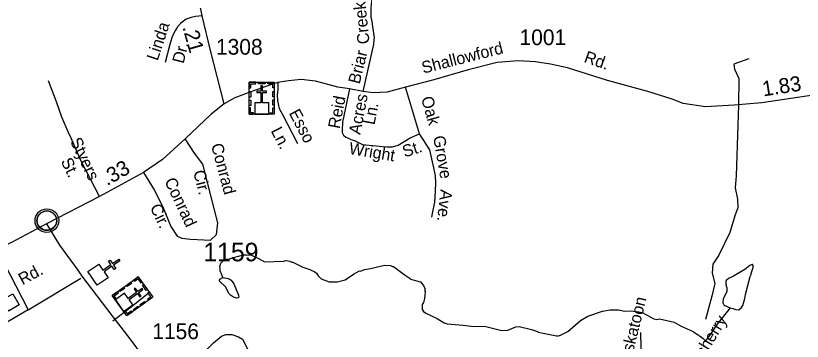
# Model space of a CAD drawing. Extents: x 1547597 to 1699558, y 810033 to 920809.
# Drawn here: x 1580417 to 1586678, y 856344 to 858935 of the extents above; entities that cross this region are included whole.
import ezdxf

# ---------------------------------------------------------------- set-up
doc = ezdxf.new("R2010")
doc.units = 0
for name, color, linetype in [('Exist Civil Demographics Community CELL', 7, 'Continuous'), ('Exist Cultural Church CELL', 7, 'Continuous'), ('Exist Cultural Church with Cemetery CELL', 7, 'Continuous'), ('Exist Cultural Educational Facility Elementary CELL', 7, 'Continuous'), ('Exist Hydrographic Misc Water Feature', 7, 'Continuous'), ('Exist Road Non-System Type 51', 7, 'Continuous'), ('Exist Road Non-System Type 51 Label', 7, 'Continuous'), ('Exist Road Secondary Historical Relocated Label', 7, 'Continuous'), ('Exist Road Secondary Mileage Hundredths English Label', 7, 'Continuous'), ('Exist Road Secondary Type 51 Attributed', 7, 'Continuous'), ('Exist Road Secondary Type 51 Label', 7, 'Continuous'), ('Exist Road Secondary Type 51 Number Label', 7, 'Continuous')]:
    doc.layers.add(name, color=color, linetype=linetype)

msp = doc.modelspace()

# ---------------------------------------------------------------- linework, layer by layer
at = {"layer": 'Exist Civil Demographics Community CELL'}
msp.add_lwpolyline([(1580586.7, 857316.5), (1580587.7, 857322.1), (1580589.5, 857328.7), (1580592.4, 857335.9), (1580595.3, 857341.6), (1580598.7, 857347.4), (1580602.4, 857352.5), (1580606.4, 857356.9), (1580611, 857361.4), (1580616.5, 857366), (1580621.9, 857369.7), (1580626.8, 857372.6), (1580631.9, 857375), (1580637.3, 857377.3), (1580643, 857379.1), (1580647.3, 857380.3), (1580652.1, 857381), (1580656.3, 857381.7), (1580662.6, 857382), (1580667.1, 857381.9), (1580672.7, 857381.6), (1580677.6, 857380.9), (1580682.5, 857379.9), (1580687.5, 857378.5), (1580692.7, 857376.6), (1580699.4, 857373.7), (1580705.6, 857370.2), (1580710.7, 857366.6), (1580715.9, 857362.6), (1580719.2, 857359.5), (1580723.3, 857355.1), (1580727.1, 857350.4), (1580730.2, 857345.8), (1580733.4, 857340.8), (1580735.8, 857335.6), (1580737.8, 857330.6), (1580739.4, 857325.6), (1580740.7, 857321), (1580741.8, 857315), (1580742.4, 857310.3), (1580742.7, 857304.3), (1580742.5, 857298.5), (1580741.9, 857292.8), (1580741, 857287.3), (1580739.3, 857281.1), (1580737.5, 857275.3), (1580735.2, 857270.2), (1580732, 857264.2), (1580728.7, 857258.9), (1580725.3, 857254.2), (1580721, 857249.5), (1580715.7, 857244.5), (1580710.7, 857240.4), (1580705.7, 857236.9), (1580701.4, 857234.4), (1580694.6, 857231.2), (1580687.4, 857228.5), (1580681.5, 857227), (1580674.9, 857225.7), (1580670.5, 857225.3), (1580666, 857225), (1580660.4, 857225), (1580656.1, 857225.4), (1580650.5, 857226.1), (1580644.5, 857227.4), (1580640, 857228.8), (1580634.8, 857230.6), (1580630.2, 857232.6), (1580626.3, 857234.9), (1580619.5, 857238.9), (1580613.9, 857243.2), (1580609, 857247.7), (1580604.5, 857252.5), (1580601.3, 857256.5), (1580598.4, 857260.7), (1580594.3, 857267.8), (1580592.6, 857271.3), (1580590.8, 857275.3), (1580588.2, 857283.5), (1580586.7, 857290.6), (1580586, 857295.7), (1580585.7, 857302.1), (1580585.6, 857306.8), (1580586.2, 857313.2)], close=True, dxfattribs=at)
for centre, radius in [((1580664.3, 857304.1), 94.3), ((1580664.1, 857304.4), 76.7)]:
    msp.add_circle(centre, radius, dxfattribs=at)
at = {"layer": 'Exist Cultural Church CELL'}
msp.add_lwpolyline([(1581078.6, 856957.9), (1581110.8, 856910.9), (1581173.7, 856953.8), (1581155.7, 856980.3), (1581168.9, 856989.3), (1581186.9, 856962.8), (1581236.6, 856996.7), (1581245.6, 856983.4), (1581195.9, 856949.6), (1581214, 856923.1), (1581200.7, 856914.1), (1581182.7, 856940.6), (1581119.8, 856897.7), (1581152.2, 856850), (1581064.2, 856790.1), (1580990.7, 856898)], close=True, dxfattribs=at)
at = {"layer": 'Exist Cultural Church with Cemetery CELL'}
for points in [[(1582275.8, 858405.4), (1582474.9, 858405.4), (1582474.9, 858150.8), (1582275.8, 858150.8)], [(1582275.8, 858362.1), (1582287.2, 858362.1), (1582287.2, 858394.3), (1582327.7, 858394.3), (1582327.7, 858405.4), (1582275.8, 858405.4)], [(1582318.9, 858150.8), (1582431.1, 858150.8), (1582431.1, 858241.4), (1582380.3, 858241.4), (1582380.3, 858322.9), (1582413.3, 858322.9), (1582413.3, 858333.9), (1582380.3, 858333.9), (1582380.3, 858376.1), (1582368.7, 858376.1), (1582368.7, 858333.9), (1582335.6, 858333.9), (1582335.6, 858322.9), (1582368.7, 858322.9), (1582368.7, 858241.4), (1582318.9, 858241.4)], [(1582349.9, 858405.4), (1582401.7, 858405.4), (1582401.7, 858394), (1582349.9, 858394)], [(1582475, 858362), (1582463.6, 858362), (1582463.6, 858394.2), (1582423.1, 858394.2), (1582423.1, 858405.4), (1582475, 858405.4)], [(1582275.8, 858287.9), (1582275.8, 858331.2), (1582287.2, 858331.2), (1582287.2, 858287.9)], [(1582463.6, 858289), (1582463.6, 858332.3), (1582475, 858332.3), (1582475, 858289)], [(1582275.8, 858220.7), (1582275.8, 858264), (1582287.2, 858264), (1582287.2, 858220.7)], [(1582463.5, 858223), (1582463.5, 858266.4), (1582474.9, 858266.4), (1582474.9, 858223)], [(1582308.9, 858150.8), (1582308.9, 858162.3), (1582286.9, 858162.3), (1582286.9, 858202.7), (1582275.8, 858202.7), (1582275.8, 858150.8)], [(1582441.8, 858150.8), (1582441.8, 858162.3), (1582463.8, 858162.3), (1582463.8, 858202.7), (1582474.9, 858202.7), (1582474.9, 858150.8)], [(1581391.7, 856856.8), (1581507.9, 856695.1), (1581301.2, 856546.5), (1581185, 856708.2)], [(1581296.3, 856788.2), (1581331.5, 856813.5), (1581338.1, 856804.3), (1581303, 856779)], [(1581356.5, 856831.5), (1581363.2, 856822.3), (1581389.3, 856841.1), (1581413, 856808.1), (1581422, 856814.6), (1581391.7, 856856.8)], [(1581210.1, 856673.2), (1581275.6, 856582.1), (1581349.1, 856635), (1581319.5, 856676.2), (1581385.7, 856723.8), (1581404.9, 856697), (1581413.9, 856703.4), (1581394.6, 856730.2), (1581428.9, 856754.8), (1581422.1, 856764.2), (1581387.8, 856739.6), (1581368.5, 856766.5), (1581359.6, 856760.1), (1581378.9, 856733.2), (1581312.8, 856685.6), (1581283.7, 856726.1)], [(1581241.7, 856749), (1581276.9, 856774.3), (1581283.5, 856765.1), (1581248.4, 856739.8)], [(1581434.9, 856796.6), (1581465.2, 856754.5), (1581455.9, 856747.9), (1581425.7, 856790)], [(1581204.3, 856681.3), (1581213.6, 856688), (1581200.8, 856705.9), (1581233.6, 856729.5), (1581227.1, 856738.5), (1581185, 856708.2)], [(1581472.7, 856669.8), (1581466.1, 856679), (1581492.3, 856697.8), (1581468.6, 856730.7), (1581477.6, 856737.2), (1581507.9, 856695)], [(1581353.2, 856597.9), (1581388.4, 856623.2), (1581395, 856614), (1581359.8, 856588.7)], [(1581406.7, 856636.4), (1581441.9, 856661.6), (1581448.6, 856652.4), (1581413.4, 856627.1)], [(1581281.8, 856573.4), (1581291.1, 856580.1), (1581304, 856562.3), (1581336.8, 856585.8), (1581343.3, 856576.8), (1581301.2, 856546.5)]]:
    msp.add_lwpolyline(points, close=True, dxfattribs=at)
at = {"layer": 'Exist Cultural Educational Facility Elementary CELL'}
msp.add_lwpolyline([(1580444.2, 856634), (1580359.6, 856584.7), (1580336.4, 856624.5), (1580271.5, 856586.7), (1580274.3, 856533.8), (1580220.5, 856568), (1580331.6, 856632.8), (1580308.4, 856672.5), (1580393, 856721.8)], close=True, dxfattribs=at)
at = {"layer": 'Exist Hydrographic Misc Water Feature'}
for points in [[(1582066.6, 856850.8), (1582056.7, 856873.1), (1582045.1, 856905.2), (1582045.3, 856921.2), (1582041.5, 856935.3), (1582049.8, 856965.1), (1582072.1, 856988.8), (1582094.2, 856996.6), (1582118.2, 857000.3), (1582150.4, 857011.9), (1582230.6, 857030.8), (1582254.6, 857032.5), (1582294.6, 857030), (1582340, 857009.4), (1582388.9, 856982.3), (1582393.9, 856976.8), (1582549.9, 856982.8), (1582565.9, 856986.6), (1582597.9, 856982.2), (1582613.8, 856974), (1582621.8, 856973.9), (1582701.3, 856933), (1582757.1, 856916.2), (1582796.9, 856897.7), (1582810.8, 856885.6), (1582824.5, 856865.4), (1582848.2, 856841.1), (1582912, 856818.3), (1582975.9, 856817.6), (1583040, 856832.7), (1583104.6, 856877.9), (1583152.9, 856903.3), (1583160.9, 856903.2), (1583193, 856914.8), (1583241.1, 856922.1), (1583351.4, 856948.7), (1583401.3, 856948.1), (1583417.2, 856939.9), (1583425.2, 856939.8), (1583508.5, 856874.8), (1583557.4, 856842.9), (1583560, 856838.2), (1583639.8, 856817.2), (1583664.1, 856787.7), (1583676.3, 856759.8), (1583671.1, 856756.8), (1583674.9, 856740.8), (1583674.4, 856708.8), (1583670.1, 856684.8), (1583661.8, 856653), (1583653.6, 856637.1), (1583653.1, 856597.1), (1583657, 856589.1), (1583663, 856581), (1583680.8, 856568.8), (1583772.3, 856525.7), (1583827.8, 856491), (1583851.7, 856482.7), (1583979.6, 856473.1), (1584043.4, 856464.3), (1584159.4, 856462.8), (1584287, 856429.2), (1584335, 856432.6), (1584399.3, 856459.8), (1584423.4, 856461.5), (1584523.1, 856438.2), (1584571.2, 856422.7), (1584574.8, 856417.6), (1584722.5, 856387.8), (1584738.5, 856387.6), (1584754.5, 856391.4), (1584810.8, 856420.6), (1584913.9, 856509.3), (1584972.2, 856544.5), (1585088.7, 856583), (1585148.8, 856594.3), (1585216.7, 856593.4), (1585264.6, 856584.8), (1585312.7, 856586.2), (1585376.6, 856579.4), (1585408.5, 856571), (1585495.8, 856522), (1585519.8, 856517.7), (1585541.9, 856521.4), (1585659.6, 856495.9), (1585715.1, 856463.2), (1585810.6, 856422), (1585814.6, 856416), (1585850.3, 856395.6), (1585858.2, 856387.5), (1585866.1, 856385.4), (1585889.9, 856367.1), (1585908.1, 856348.1)], [(1586105.2, 856608.9), (1586124.7, 856606), (1586148.6, 856597.7), (1586172.6, 856595.4), (1586194.8, 856613.1), (1586205, 856629), (1586221.7, 856684.7), (1586226, 856716.7), (1586263.7, 856860.2), (1586271.9, 856876.1), (1586272, 856884.1), (1586288.6, 856931.8), (1586286.8, 856947.8), (1586282.8, 856953.9), (1586278.9, 856955.9), (1586260.8, 856948.1), (1586220.4, 856914.7), (1586131.8, 856861.8), (1586091.6, 856844.3), (1586073.4, 856826.5), (1586069.3, 856818.6), (1586071, 856794.6), (1586078.7, 856770.5), (1586078.3, 856738.5), (1586049.7, 856682.9), (1586045.3, 856651), (1586055.1, 856634.9), (1586063, 856628.8), (1586105.2, 856608.9)], [(1582066.6, 856850.8), (1582108.4, 856844.4), (1582124.3, 856836.2), (1582132.3, 856830.2), (1582151.8, 856799.9), (1582190.8, 856711.4), (1582192.6, 856695.5), (1582186.5, 856689.5), (1582174.5, 856687.7), (1582150.6, 856694), (1582126.8, 856710.3), (1582114.9, 856722.4), (1582085.6, 856776.8), (1582040.1, 856821.3), (1582038.2, 856829.4), (1582042.3, 856837.3), (1582066.6, 856850.8)], [(1586105.2, 856608.9), (1586001.3, 856479.6), (1585948.4, 856400.3), (1585908.1, 856348.1)]]:
    msp.add_lwpolyline(points, dxfattribs=at)
at = {"layer": 'Exist Road Non-System Type 51'}
for p, q in [((1583631.9, 857996.1), (1583518.4, 858365.6)), ((1580265.5, 857078.7), (1580515, 856593.3)), ((1580515, 856593.3), (1580934.1, 856846.3)), ((1580515, 856593.3), (1580248.8, 856437.3)), ((1582221.8, 856359.7), (1582284.1, 856240.8))]:
    msp.add_line(p, q, dxfattribs=at)
for points in [[(1583182.8, 858331.4), (1583257.6, 858661.3), (1583268.3, 858707.1), (1583270.8, 858743), (1583273, 858763), (1583258.4, 858849.4), (1583253, 858889.3), (1583247.5, 858923.4), (1583246, 858959.5), (1583246.3, 858995.5), (1583249, 859027.5), (1583255.4, 859069.5), (1583264, 859105.4), (1583272.5, 859139.2), (1583276.9, 859161.2), (1583287.5, 859199), (1583297.9, 859231), (1583306.5, 859266.8)], [(1581899.9, 858933.3), (1581846.8, 858929.8), (1581812.6, 858922.3), (1581772.5, 858906.9), (1581732, 858875.5), (1581705.7, 858847.8), (1581689.1, 858819.9), (1581664.6, 858774.4), (1581645.6, 858716.5), (1581607.4, 858563)], [(1586254.2, 858593.3), (1586134.7, 858548.5), (1586139, 858510), (1586173.1, 858435.3), (1586171, 858223.9)], [(1581083.3, 857496), (1580938.4, 857777.2), (1580856.7, 857959.8), (1580833.5, 858010.1), (1580784.9, 858128), (1580741.4, 858249.7), (1580677.7, 858417.8)], [(1582503.5, 858404), (1582502.8, 858350), (1582498.1, 858304), (1582501.4, 858260), (1582507.1, 858233.8), (1582514.6, 858197.9), (1582539.8, 858149.3), (1582660.6, 857917.5)], [(1583074.2, 858353), (1583018.3, 858088), (1583016.6, 858023.6), (1583016.3, 858005.6), (1583027.3, 857985.2), (1583043.9, 857968.5), (1583067, 857960), (1583083.5, 857951.3), (1583113.8, 857942), (1583176.8, 857911.5), (1583339.2, 857893.2), (1583371.4, 857890.7), (1583415.6, 857892.2), (1583461.7, 857905.4), (1583555.6, 857964.6), (1583631.9, 857996.1)], [(1586171, 858223.9), (1586166.7, 858063.7), (1586151.8, 857661.8), (1586145.4, 857565.7), (1586162.5, 857473.9), (1586164.6, 857405.6), (1586145.4, 857350), (1586102.7, 857209.1), (1586013.3, 857028.8), (1585966.4, 856958.3), (1585962.1, 856885.7), (1585983.4, 856804.6), (1585957.8, 856702.1), (1585908.8, 856518.4)], [(1581966.6, 857149), (1582015.3, 857195), (1582026.1, 857286.9), (1581945, 857597.9), (1581907.2, 857754.7), (1581839.7, 857841.3), (1581766.7, 857954.8)], [(1583729.7, 857330.5), (1583734.9, 857359.7), (1583752.4, 857451.6), (1583759.5, 857539.5), (1583760.5, 857605.5), (1583757.4, 857661.6), (1583746.3, 857725.6), (1583714.4, 857868.2), (1583631.9, 857996.1)], [(1581434.4, 857687.1), (1581518.2, 857549.2), (1581585.7, 857419.4), (1581650.5, 857257.2), (1581701.9, 857181.5), (1581739.7, 857165.2), (1581807.2, 857157.1), (1581966.6, 857149)], [(1581190.5, 856507.5), (1581335.3, 856617.7), (1581471.5, 856727.8)], [(1581438.2, 856179.9), (1581486, 856214.7), (1581567.1, 856235), (1581619.2, 856240.8), (1581685.9, 856217.6), (1581755.4, 856197.3), (1581796, 856194.4), (1581845.2, 856203.1), (1581897.4, 856237.9), (1581990.1, 856330.7), (1582053.8, 856385.7), (1582088.6, 856397.3), (1582137.8, 856397.3), (1582190, 856379.9), (1582221.8, 856359.7)], [(1585390.7, 856414.6), (1585392.5, 856289.7), (1585372.9, 856134.6)]]:
    msp.add_lwpolyline(points, dxfattribs=at)
at = {"layer": 'Exist Road Secondary Type 51 Attributed'}
for points in [[(1582077, 858233), (1581966.3, 858658.5), (1581899.9, 858933.3), (1581886.6, 858999.7), (1581873.3, 859123.8), (1581894, 859227.3)], [(1586766.4, 858304.2), (1586356.5, 858241), (1586136.7, 858223), (1585908, 858210.4), (1585729.8, 858237.2), (1585641.5, 858271.5), (1585449.7, 858330.9), (1585127.3, 858419.3), (1584809.5, 858520.2), (1584674.4, 858549), (1584555.6, 858567), (1584416.9, 858576.1), (1584248.1, 858561.7), (1584019.3, 858505.8), (1583745.5, 858424.7), (1583518.4, 858365.6), (1583374.8, 858326), (1583261.3, 858320.6), (1583182.8, 858331.4), (1583074.2, 858353), (1582981.1, 858367.4), (1582802.7, 858414.3), (1582689.3, 858426.9), (1582588.4, 858416.1), (1582503.5, 858404), (1582453.3, 858387.3), (1582289.4, 858329.6), (1582161.5, 858280.9), (1582077, 858233)], [(1582077, 858233), (1581972, 858152.6), (1581766.7, 857954.8), (1581585.8, 857791.2), (1581434.4, 857687.1), (1581083.3, 857496), (1580661, 857279.2)], [(1580661, 857279.2), (1580384.2, 857130.2), (1580265.5, 857078.7), (1580172.6, 857036.3), (1580080.4, 856987.7), (1579807.4, 856837), (1579681.7, 856779.9), (1579542.2, 856705.8), (1579438.7, 856638.1), (1579340, 856585.4), (1579277.3, 856557.6), (1579119.8, 856466.2), (1578923.9, 856398.8), (1578736.4, 856317.6), (1578668.2, 856288.3), (1578502.6, 856229.1), (1578279.3, 856149.5), (1578203.1, 856124.1)], [(1580661, 857279.2), (1580763.8, 857110.2), (1580910.7, 856910), (1580943.1, 856861.3), (1581182.4, 856549.2), (1581306.1, 856387.5), (1581459.7, 856183.6)]]:
    msp.add_lwpolyline(points, dxfattribs=at)

# ---------------------------------------------------------------- texts
at = {"layer": 'Exist Road Non-System Type 51 Label'}
for s, rotation, p in [('Creek', 95.85868, (1583234.1, 858713.7)), ('Linda', 71.83331, (1581546.3, 858571.5)), ('Dr.', 76.02544, (1581752.8, 858549.8)), ('Briar', 76.20859, (1583154.1, 858386.6)), ('Reid', 79.17683, (1582994.7, 858031.1)), ('Acres', 79.17683, (1583159.6, 857984.5)), ('Oak', 285.90414, (1583642.8, 858279.2)), ('Esso', 297.52576, (1582588.9, 858161.6)), ('Ln.', 79.17683, (1583272.6, 858061.9)), ('Ln.', 297.52576, (1582444.7, 858019.8)), ('Styers', 295.54909, (1580846.8, 857938.8)), ('Grove', 279.83866, (1583739.1, 857972.7)), ('Conrad', 284.97251, (1581970.5, 857906.1)), ('Wright', 350.60721, (1583064.9, 857835.3)), ('St.', 17.66637, (1583512.6, 857806.5)), ('St.', 295.54909, (1580773.4, 857777.9)), ('Cir.', 283.96791, (1581828.9, 857693.9)), ('Conrad', 295.15969, (1581598.5, 857620)), ('Ave.', 263.54571, (1583799, 857555.1)), ('Cir.', 295.15969, (1581482.6, 857411.7)), ('Saskatoon', 76.18466, (1585295.5, 856102.3)), ('Chockecherry', 58.7138, (1585675.8, 855844))]:
    msp.add_text(s, height=95, rotation=rotation, dxfattribs=at).set_placement(p)
at = {"layer": 'Exist Road Secondary Historical Relocated Label'}
msp.add_text('1159', height=147.64, dxfattribs=at).set_placement((1581910, 856980.6))
at = {"layer": 'Exist Road Secondary Mileage Hundredths English Label'}
for s, rotation, p in [('.21', 285.96926, (1581742.2, 858844)), ('1.83', 8.75483, (1586368.7, 858292.7)), ('.33', 29.63687, (1581143.6, 857578.3))]:
    msp.add_text(s, height=120, rotation=rotation, dxfattribs=at).set_placement(p)
at = {"layer": 'Exist Road Secondary Type 51 Label'}
for s, rotation, p in [('Shallowford', 14.28605, (1583661.4, 858473.5)), ('Rd.', 340.40107, (1584934.4, 858568.8)), ('Rd.', 28.45581, (1580470.3, 856788.8))]:
    msp.add_text(s, height=95, rotation=rotation, dxfattribs=at).set_placement(p)
at = {"layer": 'Exist Road Secondary Type 51 Number Label'}
for s, p in [('1001', (1584427.3, 858701.4)), ('1308', (1582010.4, 858625.3)), ('1156', (1581503.4, 856360.8))]:
    msp.add_text(s, height=125, dxfattribs=at).set_placement(p)

doc.saveas('drawing.dxf')
